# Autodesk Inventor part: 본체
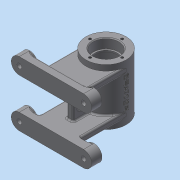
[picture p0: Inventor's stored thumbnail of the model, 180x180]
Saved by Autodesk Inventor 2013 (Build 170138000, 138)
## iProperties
Created: 2015-11
Part Number: 본체
Material: 일반
Document SubType Name: Modeling
Designer: Administrator
Density: 1 g/cm^3
Author: Administrator
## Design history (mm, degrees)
sketch "스케치1"
  geometry: C1 r 25 at (0, 0); 1 further point
  constraints: 1 centre point, 1 coincident
  dimensions: "d0" = 50 diameter of C1
extrude "돌출1" new body sketch "스케치1" stored distance "d2" = 70; taper "d3" = 0 deg
sketch "스케치2"
  geometry: C1 r 21 at (0, 0); 1 further point
  constraints: 1 centre point, 1 coincident
  dimensions: "d4" = 42 diameter of C1
extrude "돌출2" cut sketch "스케치2" stored distance "d6" = 42; taper "d7" = 0 deg
hole "구멍1" diameter "d10" = 28; stored, may be unused: countersink angle "d14" = 90 deg, drill point angle "d16" = 0 deg; dims "d8" = 10, "d9" = 10, "d11" = 6, "d12" = 32, "d13" = 12, "d15" = 14
sketch "스케치3"
  geometry: C1 r 16 at (0, 0) reference; 1 further point
  constraints: 1 vertical alignment
  dimensions: "d17" = 20 distance of point (0, 20) C1.centre
hole "구멍2" sketch "스케치3" at (0, 20) diameter "d18" = 3.242; stored, may be unused: countersink angle "d22" = 90 deg, drill point angle "d24" = 118 deg; dims "d19" = 8, "d20" = 32, "d21" = 12, "d23" = 10
node "작업 평면1"
sketch "스케치4"
  geometry: C1 r 5 at (0, 0); 1 further point
  constraints: 1 centre point, 1 coincident
  dimensions: "d29" = 10 diameter of C1
extrude "돌출3" join sketch "스케치4" stored distance "d31" = 42; taper "d32" = 0 deg
hole "구멍3" diameter "d35" = 5.188; stored, may be unused: countersink angle "d39" = 90 deg, drill point angle "d41" = 0 deg; dims "d33" = 10, "d34" = 10, "d36" = 8, "d37" = 32, "d38" = 12, "d40" = 10
sketch "스케치5"
  geometry: L1 (0, 0)-(-14, -24.249); L2 (0, 0)-(28, 0)
  constraints: 4 end point, 1 equal length, 1 horizontal
  dimensions: "d42" = 28 distance of L1.start L1.end; "d43" = 120 deg angle of L1 L2
node "작업 평면2"
sketch "스케치6"
  geometry: C1 r 6 at (0, 0); 1 further point
  constraints: 1 centre point, 1 coincident
  dimensions: "d44" = 12 diameter of C1
extrude "돌출4" join sketch "스케치6" stored distance "d46" = 42; taper "d47" = 0 deg
hole "구멍4" diameter "d50" = 5.188; stored, may be unused: countersink angle "d54" = 90 deg, drill point angle "d56" = 0 deg; dims "d48" = 10, "d49" = 10, "d51" = 8, "d52" = 32, "d53" = 12, "d55" = 10
node "작업 평면3"
sketch "스케치7"
  geometry: L1 (40, 20)-(-40, 20); L2 (-40, 20)-(-40, 40); L3 (-40, 40)-(40, 40); L4 (40, 40)-(40, 20); C1 r 10 at (40, 30); 3 further points
  constraints: 8 end point, 3 midpoint, 2 parallel, 2 vertical alignment, 1 centre point, 1 horizontal, 1 perpendicular, 2 other
  dimensions: "d58" = 20 distance of L1.end L2.end; "d60" = 40 distance from line of L3 point (0, 0); "d61" = 80 distance of L2.end L3.end; "d62" = 10 radius of C1
extrude "돌출5" join sketch "스케치7" distance "d63" = 13; taper "d64" = 0 deg
extrude "돌출6" join sketch "스케치7" distance "d65" = 10; taper "d66" = 0 deg
sketch "스케치8"
  geometry: L1 (0, 10)-(80, 10) reference; L2 (0, 10)-(80, 10) reference; L3 (80, 0)-(80, 10) reference; L4 (80, 0)-(0, 0) reference; L5 (0, 0)-(0, 10) reference; L6 (0, 10)-(0, 13) reference; L7 (80, 10)-(80, 13) reference; L8 (65, 68)-(65, 10); L9 (15, 68)-(15, 10); C1 r 21 at (40, 68) reference; A1 r 25 centre (40, 68) between (65, 68) and (15, 68) reference; 1 further point
  constraints: 4 end point, 2 perpendicular, 2 point on circle, 2 point on line, 2 tangent
extrude "돌출7" join sketch "스케치8" distance "d67" = 8; taper "d68" = 0 deg
hole "구멍5" diameter "d71" = 6; stored, may be unused: countersink angle "d75" = 90 deg, drill point angle "d77" = 0 deg; dims "d69" = 10, "d70" = 10, "d72" = 8, "d73" = 12, "d74" = 4, "d76" = 10
sketch "스케치9"
  geometry: L1 (0, 10)-(0, 0) reference; L2 (36, 43.322)-(36, 23); L3 (36, 23)-(44, 23); L4 (44, 23)-(44, 43.322); A1 r 25 centre (40, 68) between (15, 68) and (65, 68) reference; 1 further point
  constraints: 6 end point, 2 parallel, 2 point on circle, 1 midpoint, 1 perpendicular, 1 vertical alignment
  dimensions: "d78" = 8 distance of L2.end L3.end; "d80" = 45 distance from line of L3 A1.centre
extrude "돌출8" join sketch "스케치9" stored distance "d81" = 8; taper "d82" = 0 deg
sketch "스케치10"
  geometry: L1 (20, -23)-(0, -23) reference; L2 (-28, 13.5)-(-12, 13.5); L3 (-12, 6.5)-(-28, 6.5); A1 r 3.5 centre (-12, 10) between (-12, 6.5) and (-12, 13.5); A2 r 3.5 centre (-28, 10) between (-28, 13.5) and (-28, 6.5); 2 further points
  constraints: 4 end point, 4 point on circle, 4 tangent, 2 centre point, 1 equal radius, 1 horizontal alignment, 1 midpoint, 1 vertical alignment
  dimensions: "d83" = 7 diameter of A1; "d87" = 33 distance from line of L1 A1.centre; "d108" = 23 dimension on A1 A2
extrude "돌출9" cut sketch "스케치10" stored distance "d88" = 8; taper "d89" = 0 deg
node "작업 평면4"
sketch "스케치11"
  geometry: 2 further points
  constraints: 1 coincident, 1 other
feature "엠보싱1" sketch "스케치11" dims "d90" = 0.5, "d91" = 0
fillet "모깎기1" dims "d92" = 0.3
chamfer "모따기1" distance "d93" = 1; stored, may be unused: second distance "d94" = 2, angle "d95" = 45 deg
fillet "모깎기2" dims "d96" = 0.3
chamfer "모따기2" distance "d97" = 1; stored, may be unused: second distance "d98" = 2, angle "d99" = 45 deg
fillet "모깎기3" dims "d100" = 3
fillet "모깎기4" dims "d101" = 2
fillet "모깎기5" dims "d102" = 2
fillet "모깎기6" dims "d103" = 2
fillet "모깎기7" dims "d104" = 2
fillet "모깎기8" dims "d105" = 2
fillet "모깎기9" dims "d106" = 2
fillet "모깎기10" dims "d107" = 2
node "솔리드1"
pattern_circular "원형 패턴1" dims angle "d26" = 360 deg
mirror "대칭1"
mirror "대칭2"
mirror "대칭3"
node "절단 모서리 투영1"
other parameters: "d28" = 28, "d57" = -68
